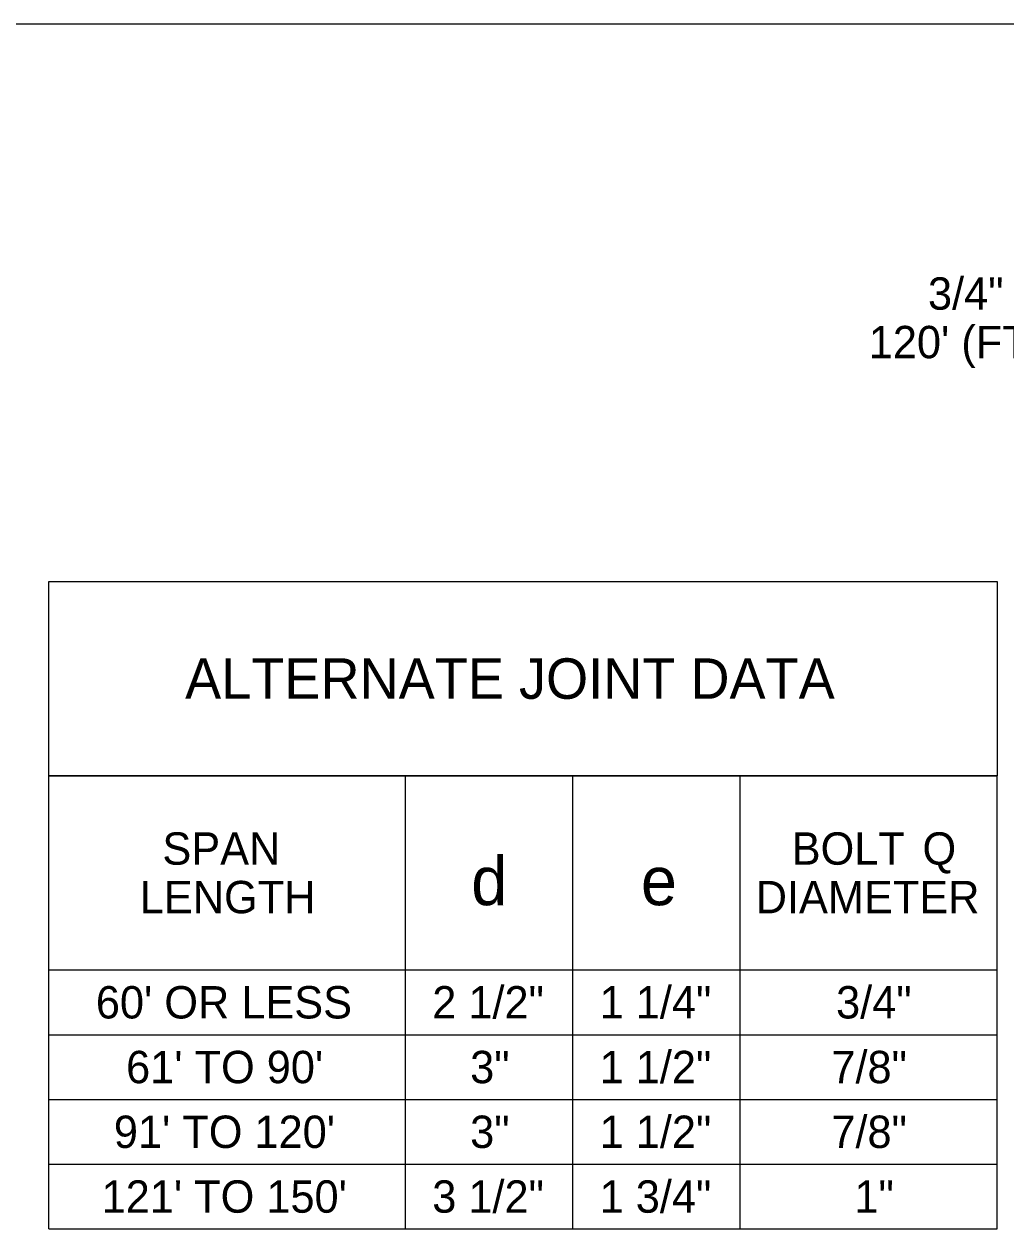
# Model space of a CAD drawing. Extents: x 99862 to 104211, y 98939 to 111076.
# Drawn here: x 101228 to 101713, y 107480 to 108075 of the extents above; entities that cross this region are included whole.
import ezdxf

# ---------------------------------------------------------------- set-up
doc = ezdxf.new("R2010")
doc.units = 0
for name, color, linetype in [('Level 15', 7, 'Continuous'), ('Level 20', 7, 'Continuous'), ('Level 40', 7, 'Continuous'), ('Level 60', 7, 'Continuous')]:
    doc.layers.add(name, color=color, linetype=linetype)

msp = doc.modelspace()

# ---------------------------------------------------------------- linework, layer by layer
at = {"layer": 'Level 40'}
for p, q in [((101239.9, 107703.52), (101708.34, 107703.52)), ((101239.9, 107607.52), (101239.9, 107703.52)), ((101416, 107479.52), (101416, 107703.52)), ((101498.71, 107479.52), (101498.71, 107703.52)), ((101581.41, 107479.52), (101581.41, 107703.52)), ((101708.34, 107479.52), (101708.34, 107703.52)), ((101239.9, 107607.52), (101708.34, 107607.52)), ((101239.9, 107479.52), (101239.9, 107607.52)), ((101239.9, 107575.52), (101708.34, 107575.52)), ((101239.9, 107543.52), (101708.34, 107543.52)), ((101239.9, 107511.52), (101708.34, 107511.52)), ((101239.9, 107479.52), (101708.34, 107479.52))]:
    msp.add_line(p, q, dxfattribs=at)
msp.add_lwpolyline([(101239.9, 107799.52), (101708.34, 107799.52), (101708.34, 107703.52), (101239.9, 107703.52)], close=True, dxfattribs=at)
at = {"layer": 'Level 60'}
msp.add_line((103150, 108075), (100000, 108075), dxfattribs=at)

# ---------------------------------------------------------------- texts
at = {"layer": 'Level 15'}
for s, p in [('3/4" (IN) FOR SPANS OVER', (101674.18, 107933.84)), ('120\' (FT) OTHERWISE 3/8" (IN)', (101644.93, 107909.84))]:
    msp.add_text(s, height=16, dxfattribs=at).set_placement(p)
at = {"layer": 'Level 20'}
msp.add_text('ALTERNATE JOINT DATA', height=20, rotation=360, dxfattribs=at).set_placement((101307.16, 107741.52))
for s, height, p in [('SPAN ', 16, (101295.95, 107659.52)), ('BOLT   ', 16, (101606.85, 107659.52)), ('Q', 16, (101671.46, 107659.52)), ('d', 24, (101448.53, 107639.52)), (' e ', 24, (101523.44, 107639.52)), ('LENGTH', 16, (101284.78, 107635.52)), ('DIAMETER', 16, (101589.07, 107635.52)), ("60' OR LESS", 16, (101263.07, 107583.52)), ('2 1/2"', 16, (101429.27, 107583.52)), ('1 1/4"', 16, (101511.97, 107583.52)), (' 3/4"', 16, (101622.83, 107583.52)), ('1 1/2"', 16, (101511.97, 107551.52)), ('7/8"', 16, (101626.45, 107551.52)), ("61' TO 90'", 16, (101278.02, 107551.52)), ('3"', 16, (101447.99, 107551.52)), ("91' TO 120'", 16, (101271.97, 107519.52)), ('3"', 16, (101447.99, 107519.52)), ('1 1/2"', 16, (101511.97, 107519.52)), ('7/8"', 16, (101626.45, 107519.52)), ("121' TO 150'", 16, (101265.93, 107487.52)), ('3 1/2"', 16, (101429.27, 107487.52)), ('1 3/4"', 16, (101511.97, 107487.52)), (' 1"', 16, (101631.89, 107487.52))]:
    msp.add_text(s, height=height, dxfattribs=at).set_placement(p)

doc.saveas('drawing.dxf')
